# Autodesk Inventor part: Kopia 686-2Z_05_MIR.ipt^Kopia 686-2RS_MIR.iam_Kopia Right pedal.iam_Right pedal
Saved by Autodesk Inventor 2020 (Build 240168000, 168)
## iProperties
Created: 2017-10
Part Number: Kopia 686-2Z_05_MIR.ipt^Kopia 686-2RS_MIR.iam_Kopia Right pedal.iam_Right pedal
Material: Ogólny
Document SubType Name: Modeling
Designer: Tomasz
Density: 1 g/cm^3
Appearance: Domyślna
Sending System: SolidWorks 2017
Last Author: Tomasz
Last Saved: 2017-10-01
Author: Tomasz
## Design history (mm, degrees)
